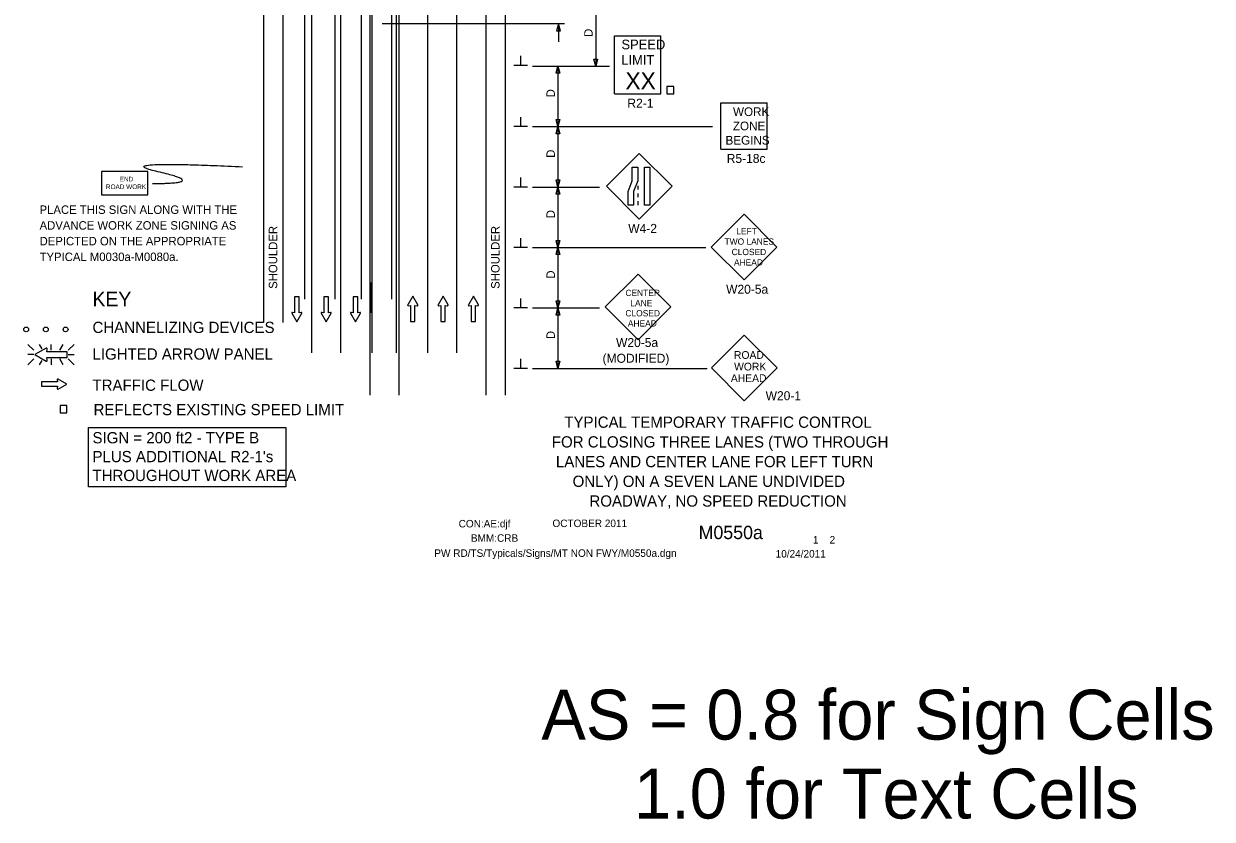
# Model space of a CAD drawing. Extents: x 16731 to 18475, y 7003 to 8262.
# Drawn here: x 16731 to 17714, y 7003 to 7661 of the extents above; entities that cross this region are included whole.
import ezdxf

# ---------------------------------------------------------------- set-up
doc = ezdxf.new("R2010")
doc.units = 0
for name, color, linetype in [('ALI_LEGAL_EX', 7, 'Continuous'), ('BORDER', 7, 'Continuous'), ('BORDER_SIGNAL_WO', 7, 'Continuous'), ('MT_SCRATCH_LEVEL_E', 7, 'Continuous'), ('PAVT_EDGE_EX', 7, 'Continuous'), ('TRAFFIC_SIGNS_PR', 7, 'Continuous'), ('TYPICAL_TEXT_DIMEN_EX', 7, 'Continuous'), ('TYPICAL_TEXT_DIMEN_PR', 7, 'Continuous')]:
    doc.layers.add(name, color=color, linetype=linetype)

msp = doc.modelspace()

# ---------------------------------------------------------------- linework, layer by layer
at = {"layer": 'ALI_LEGAL_EX'}
for p, q in [((16969.24, 7388.68), (16969.24, 8211.76)), ((16993.24, 7388.68), (16993.24, 8211.76)), ((17019.24, 7388.68), (17019.24, 8211.76)), ((17039.24, 7388.68), (17039.24, 8211.76)), ((17065.24, 7388.68), (17065.24, 8211.76)), ((17089.24, 7388.68), (17089.24, 8211.76))]:
    msp.add_line(p, q, dxfattribs=at)
for points in [[(16969.24, 7588.68), (16969.24, 7613.68)], [(16993.24, 7588.68), (16993.24, 7613.68)], [(17019.24, 7588.68), (17019.24, 7613.68)], [(17039.24, 7588.68), (17039.24, 7613.68)], [(17065.24, 7588.68), (17065.24, 7613.68)], [(17089.24, 7588.68), (17089.24, 7613.68)], [(16969.24, 7488.68), (16969.24, 7513.68)], [(16993.24, 7488.68), (16993.24, 7513.68)], [(17019.24, 7488.68), (17019.24, 7513.68)], [(17039.24, 7488.68), (17039.24, 7513.68)], [(17065.24, 7488.68), (17065.24, 7513.68)], [(17089.24, 7488.68), (17089.24, 7513.68)], [(17019.24, 7388.68), (17019.24, 7413.68)], [(17039.24, 7388.68), (17039.24, 7413.68)], [(17065.24, 7388.68), (17065.24, 7413.68)], [(17089.24, 7388.68), (17089.24, 7413.68)]]:
    msp.add_lwpolyline(points, dxfattribs=at)
at = {"layer": 'MT_SCRATCH_LEVEL_E'}
for p, q in [((16958.65, 7435.14), (16954.91, 7435.14)), ((16954.91, 7435.14), (16954.91, 7421.89)), ((16958.65, 7435.14), (16954.91, 7435.14)), ((16954.91, 7435.14), (16954.91, 7421.89)), ((16958.65, 7421.89), (16958.65, 7435.14)), ((16958.65, 7421.89), (16958.65, 7435.14)), ((16982.91, 7435.14), (16979.17, 7435.14)), ((16979.17, 7435.14), (16979.17, 7421.89)), ((16982.91, 7435.14), (16979.17, 7435.14)), ((16979.17, 7435.14), (16979.17, 7421.89)), ((16982.91, 7421.89), (16982.91, 7435.14)), ((16982.91, 7421.89), (16982.91, 7435.14)), ((17007.16, 7435.14), (17003.42, 7435.14)), ((17003.42, 7435.14), (17003.42, 7421.89)), ((17007.16, 7435.14), (17003.42, 7435.14)), ((17003.42, 7435.14), (17003.42, 7421.89)), ((17007.16, 7421.89), (17007.16, 7435.14)), ((17007.16, 7421.89), (17007.16, 7435.14)), ((17052.67, 7435.6), (17048.56, 7428.36)), ((17052.67, 7435.6), (17048.56, 7428.36)), ((17056.82, 7428.36), (17052.67, 7435.6)), ((17056.82, 7428.36), (17052.67, 7435.6)), ((17077.76, 7435.6), (17073.65, 7428.36)), ((17077.76, 7435.6), (17073.65, 7428.36)), ((17081.91, 7428.36), (17077.76, 7435.6)), ((17081.91, 7428.36), (17077.76, 7435.6)), ((17102.85, 7435.6), (17098.74, 7428.36)), ((17102.85, 7435.6), (17098.74, 7428.36)), ((17107, 7428.36), (17102.85, 7435.6)), ((17107, 7428.36), (17102.85, 7435.6)), ((17049.05, 7427.68), (17050.82, 7427.99)), ((17049.05, 7427.68), (17050.82, 7427.99)), ((17050.82, 7427.99), (17050.82, 7414.74)), ((17050.82, 7427.99), (17050.82, 7414.74)), ((17054.56, 7414.74), (17054.56, 7427.99)), ((17054.56, 7427.99), (17056.34, 7427.68)), ((17054.56, 7414.74), (17054.56, 7427.99)), ((17054.56, 7427.99), (17056.34, 7427.68)), ((17074.14, 7427.68), (17075.91, 7427.99)), ((17074.14, 7427.68), (17075.91, 7427.99)), ((17075.91, 7427.99), (17075.91, 7414.74)), ((17075.91, 7427.99), (17075.91, 7414.74)), ((17079.65, 7414.74), (17079.65, 7427.99)), ((17079.65, 7427.99), (17081.43, 7427.68)), ((17079.65, 7414.74), (17079.65, 7427.99)), ((17079.65, 7427.99), (17081.43, 7427.68)), ((17099.22, 7427.68), (17101, 7427.99)), ((17099.22, 7427.68), (17101, 7427.99)), ((17101, 7427.99), (17101, 7414.74)), ((17101, 7427.99), (17101, 7414.74)), ((17104.74, 7414.74), (17104.74, 7427.99)), ((17104.74, 7427.99), (17106.52, 7427.68)), ((17104.74, 7414.74), (17104.74, 7427.99)), ((17104.74, 7427.99), (17106.52, 7427.68)), ((16952.65, 7421.52), (16956.8, 7414.28)), ((16952.65, 7421.52), (16956.8, 7414.28)), ((16954.91, 7421.89), (16953.13, 7422.2)), ((16954.91, 7421.89), (16953.13, 7422.2)), ((16956.8, 7414.28), (16960.91, 7421.52)), ((16956.8, 7414.28), (16960.91, 7421.52)), ((16960.43, 7422.2), (16958.65, 7421.89)), ((16960.43, 7422.2), (16958.65, 7421.89)), ((16976.91, 7421.52), (16981.06, 7414.28)), ((16976.91, 7421.52), (16981.06, 7414.28)), ((16979.17, 7421.89), (16977.39, 7422.2)), ((16979.17, 7421.89), (16977.39, 7422.2)), ((16981.06, 7414.28), (16985.17, 7421.52)), ((16981.06, 7414.28), (16985.17, 7421.52)), ((16984.69, 7422.2), (16982.91, 7421.89)), ((16984.69, 7422.2), (16982.91, 7421.89)), ((17001.17, 7421.52), (17005.31, 7414.28)), ((17001.17, 7421.52), (17005.31, 7414.28)), ((17003.42, 7421.89), (17001.64, 7422.2)), ((17003.42, 7421.89), (17001.64, 7422.2)), ((17005.31, 7414.28), (17009.42, 7421.52)), ((17005.31, 7414.28), (17009.42, 7421.52)), ((17008.94, 7422.2), (17007.16, 7421.89)), ((17008.94, 7422.2), (17007.16, 7421.89)), ((17050.82, 7414.74), (17054.56, 7414.74)), ((17050.82, 7414.74), (17054.56, 7414.74)), ((17075.91, 7414.74), (17079.65, 7414.74)), ((17075.91, 7414.74), (17079.65, 7414.74)), ((17101, 7414.74), (17104.74, 7414.74)), ((17101, 7414.74), (17104.74, 7414.74)), ((16758.95, 7364.79), (16745.69, 7364.79)), ((16745.69, 7364.79), (16745.69, 7361.05)), ((16758.95, 7364.79), (16745.69, 7364.79)), ((16745.69, 7364.79), (16745.69, 7361.05)), ((16758.63, 7366.57), (16758.95, 7364.79)), ((16758.63, 7366.57), (16758.95, 7364.79)), ((16766.56, 7362.94), (16759.32, 7367.05)), ((16766.56, 7362.94), (16759.32, 7367.05)), ((16745.69, 7361.05), (16758.95, 7361.05)), ((16745.69, 7361.05), (16758.95, 7361.05)), ((16758.95, 7361.05), (16758.63, 7359.27)), ((16758.95, 7361.05), (16758.63, 7359.27)), ((16759.32, 7358.79), (16766.56, 7362.94)), ((16759.32, 7358.79), (16766.56, 7362.94))]:
    msp.add_line(p, q, dxfattribs=at)
for centre, start, end in [((17048.97, 7428.14), 150.42484, 279.96381), ((17048.97, 7428.14), 150.42484, 279.96381), ((17056.41, 7428.14), 260.03619, 29.77312), ((17056.41, 7428.14), 260.03619, 29.77312), ((17074.06, 7428.14), 150.42484, 279.96381), ((17074.06, 7428.14), 150.42484, 279.96381), ((17081.5, 7428.14), 260.03619, 29.77312), ((17081.5, 7428.14), 260.03619, 29.77312), ((17099.15, 7428.14), 150.42484, 279.96381), ((17099.15, 7428.14), 150.42484, 279.96381), ((17106.59, 7428.14), 260.03619, 29.77312), ((17106.59, 7428.14), 260.03619, 29.77312), ((16953.06, 7421.74), 80.03619, 209.77312), ((16953.06, 7421.74), 80.03619, 209.77312), ((16960.5, 7421.74), 330.42484, 99.96381), ((16960.5, 7421.74), 330.42484, 99.96381), ((16977.32, 7421.74), 80.03619, 209.77312), ((16977.32, 7421.74), 80.03619, 209.77312), ((16984.76, 7421.74), 330.42484, 99.96381), ((16984.76, 7421.74), 330.42484, 99.96381), ((17001.57, 7421.74), 80.03619, 209.77312), ((17001.57, 7421.74), 80.03619, 209.77312), ((17009.02, 7421.74), 330.42484, 99.96381), ((17009.02, 7421.74), 330.42484, 99.96381), ((16759.09, 7366.64), 60.42484, 189.96381), ((16759.09, 7366.64), 60.42484, 189.96381), ((16759.09, 7359.2), 170.03619, 299.77312), ((16759.09, 7359.2), 170.03619, 299.77312)]:
    msp.add_arc(centre, 0.463, start, end, dxfattribs=at)
at = {"layer": 'PAVT_EDGE_EX'}
for p, q in [((16963.15, 8262.34), (16963.15, 7433.15)), ((16988.15, 8262.34), (16988.15, 7433.15)), ((17010.15, 8262.34), (17010.15, 7433.15)), ((17035.15, 8262.34), (17035.15, 7433.15)), ((16929.24, 8211.76), (16929.24, 7413.89)), ((16945.24, 8211.76), (16945.24, 7413.89)), ((17017.24, 8211.76), (17017.24, 7353.85)), ((17041.24, 8211.76), (17041.24, 7353.85)), ((17113.24, 8211.76), (17113.24, 7353.85)), ((17129.24, 8211.76), (17129.24, 7353.85))]:
    msp.add_line(p, q, dxfattribs=at)
for points in [[(16993.24, 7421.93), (16993.24, 7446.93)], [(17018.24, 7421.93), (17018.24, 7446.93)]]:
    msp.add_lwpolyline(points, dxfattribs=at)
at = {"layer": 'TRAFFIC_SIGNS_PR'}
for p, q in [((17219.61, 7650.98), (17258.01, 7650.98)), ((17219.61, 7602.98), (17219.61, 7650.98)), ((17258.01, 7602.98), (17258.01, 7650.98)), ((17219.61, 7602.98), (17258.01, 7602.98)), ((17307.65, 7557.26), (17307.65, 7595.66)), ((17307.65, 7595.66), (17346.05, 7595.66)), ((17346.05, 7557.26), (17346.05, 7595.66)), ((17240.04, 7553.68), (17212.89, 7526.53)), ((17267.19, 7526.53), (17240.04, 7553.68)), ((17307.65, 7557.26), (17346.05, 7557.26)), ((17212.89, 7526.53), (17240.04, 7499.38)), ((17238.79, 7527.02), (17238.79, 7523.82)), ((17240.04, 7499.38), (17267.19, 7526.53)), ((17238.79, 7520.62), (17238.79, 7517.42)), ((17238.79, 7514.22), (17238.79, 7511.02)), ((17326.8, 7503.39), (17299.65, 7476.23)), ((17353.96, 7476.23), (17326.8, 7503.39)), ((17299.65, 7476.23), (17326.8, 7449.08)), ((17326.8, 7449.08), (17353.96, 7476.23)), ((17239.08, 7453.85), (17211.93, 7426.7)), ((17266.23, 7426.7), (17239.08, 7453.85)), ((17211.93, 7426.7), (17239.08, 7399.55)), ((17239.08, 7399.55), (17266.23, 7426.7)), ((17326.91, 7403.39), (17299.76, 7376.24)), ((17354.07, 7376.24), (17326.91, 7403.39)), ((16734.42, 7395.74), (16739.35, 7390.81)), ((16746.18, 7391.92), (16743.98, 7395.75)), ((16753.5, 7390.81), (16753.5, 7395.75)), ((16760.74, 7390.81), (16763.59, 7395.75)), ((16767.65, 7390.81), (16772.59, 7395.75)), ((16739.35, 7387.26), (16734.42, 7387.26)), ((16734.42, 7378.77), (16739.35, 7383.7)), ((16753.5, 7383.7), (16753.5, 7378.77)), ((16763.63, 7378.77), (16760.78, 7383.7)), ((16767.65, 7387.26), (16772.59, 7387.26)), ((16767.65, 7383.7), (16772.59, 7378.76)), ((16743.93, 7378.77), (16746.04, 7382.43)), ((17299.76, 7376.24), (17326.91, 7349.09)), ((17326.91, 7349.09), (17354.07, 7376.24))]:
    msp.add_line(p, q, dxfattribs=at)
for points in [[(17263.02, 7602.98), (17268.62, 7602.98), (17268.62, 7609.15), (17263.02, 7609.15)], [(17238.79, 7542.27), (17238.79, 7531.09), (17235.45, 7522.2), (17235.45, 7511.02), (17230.95, 7511.02), (17230.95, 7522.2), (17234.3, 7531.09), (17234.3, 7542.27)], [(17248.93, 7542.27), (17248.93, 7511.02), (17244.44, 7511.02), (17244.44, 7542.27)], [(16795.29, 7519.44), (16833.69, 7519.44), (16833.69, 7538.64), (16795.29, 7538.64)], [(16761.02, 7338.99), (16766.61, 7338.99), (16766.61, 7345.16), (16761.02, 7345.16)]]:
    msp.add_lwpolyline(points, close=True, dxfattribs=at)
for points in [[(16749.43, 7392.53), (16740.14, 7387.26), (16749.43, 7381.94)], [(16750.31, 7382.56), (16749.9, 7384.83), (16766.92, 7384.83), (16766.92, 7389.63), (16749.9, 7389.63), (16750.31, 7391.91)]]:
    msp.add_lwpolyline(points, dxfattribs=at)
for centre in [(16732.93, 7408.1), (16749.23, 7408.1), (16765.53, 7408.1)]:
    msp.add_circle(centre, 2, dxfattribs=at)
for centre, radius, start, end in [((16749.72, 7392.01), 0.598, 350.73078, 118.89165), ((16749.72, 7382.46), 0.597, 241.48329, 9.95933)]:
    msp.add_arc(centre, radius, start, end, dxfattribs=at)
msp.add_open_spline([(16837.29, 7528.82), (16884.52, 7528.82), (16799.5, 7548.17), (16911.8, 7542.68)], degree=2, dxfattribs=at)
at = {"layer": 'TYPICAL_TEXT_DIMEN_EX'}
msp.add_lwpolyline([(16784.43, 7326.97), (16947.6, 7326.97), (16947.6, 7278.01), (16784.43, 7278.01)], close=True, dxfattribs=at)
at = {"layer": 'TYPICAL_TEXT_DIMEN_PR'}
for p, q in [((17204.09, 7675.89), (17204.09, 7625.89)), ((17178.24, 7660.97), (17027.46, 7660.97)), ((17173.24, 7660.97), (17171.67, 7655.11)), ((17173.24, 7660.97), (17173.24, 7646.05)), ((17174.81, 7655.11), (17173.24, 7660.97)), ((17171.67, 7655.11), (17173.24, 7655.11)), ((17173.24, 7655.11), (17174.81, 7655.11)), ((17142, 7626.54), (17142, 7634.33)), ((17204.09, 7625.89), (17202.52, 7631.76)), ((17202.52, 7631.76), (17204.09, 7631.76)), ((17204.09, 7631.76), (17205.66, 7631.76)), ((17205.66, 7631.76), (17204.09, 7625.89)), ((17147.62, 7626.54), (17136.37, 7626.54)), ((17151.87, 7625.89), (17215.42, 7625.89)), ((17171.3, 7620.03), (17172.87, 7625.89)), ((17172.87, 7620.03), (17171.3, 7620.03)), ((17172.87, 7625.89), (17172.87, 7575.89)), ((17172.87, 7625.89), (17174.44, 7620.03)), ((17174.44, 7620.03), (17172.87, 7620.03)), ((17142, 7575.89), (17142, 7583.68)), ((17172.87, 7575.89), (17171.3, 7581.76)), ((17171.3, 7581.76), (17172.87, 7581.76)), ((17172.87, 7581.76), (17174.44, 7581.76)), ((17174.44, 7581.76), (17172.87, 7575.89)), ((17147.62, 7575.89), (17136.37, 7575.89)), ((17151.87, 7575.89), (17300.7, 7575.89)), ((17171.3, 7570.03), (17172.87, 7575.89)), ((17172.87, 7575.89), (17172.87, 7525.89)), ((17172.87, 7575.89), (17174.44, 7570.03)), ((17172.87, 7570.03), (17171.3, 7570.03)), ((17174.44, 7570.03), (17172.87, 7570.03)), ((17142, 7525.89), (17142, 7533.68)), ((17172.87, 7525.89), (17171.3, 7531.76)), ((17171.3, 7531.76), (17172.87, 7531.76)), ((17172.87, 7531.76), (17174.44, 7531.76)), ((17174.44, 7531.76), (17172.87, 7525.89)), ((17147.62, 7525.89), (17136.37, 7525.89)), ((17151.87, 7525.89), (17207.23, 7525.89)), ((17171.3, 7520.03), (17172.87, 7525.89)), ((17172.87, 7525.89), (17172.87, 7475.89)), ((17172.87, 7525.89), (17174.44, 7520.03)), ((17172.87, 7520.03), (17171.3, 7520.03)), ((17174.44, 7520.03), (17172.87, 7520.03)), ((17142, 7475.89), (17142, 7483.68)), ((17147.62, 7475.89), (17136.37, 7475.89)), ((17151.87, 7475.89), (17295.31, 7475.89)), ((17172.87, 7475.89), (17171.3, 7481.76)), ((17171.3, 7481.76), (17172.87, 7481.76)), ((17171.3, 7470.03), (17172.87, 7475.89)), ((17172.87, 7481.76), (17174.44, 7481.76)), ((17174.44, 7481.76), (17172.87, 7475.89)), ((17172.87, 7475.89), (17172.87, 7425.89)), ((17172.87, 7475.89), (17174.44, 7470.03)), ((17172.87, 7470.03), (17171.3, 7470.03)), ((17174.44, 7470.03), (17172.87, 7470.03)), ((17142, 7425.89), (17142, 7433.68)), ((17147.62, 7425.89), (17136.37, 7425.89)), ((17151.87, 7425.89), (17207.23, 7425.89)), ((17172.87, 7425.89), (17171.3, 7431.76)), ((17171.3, 7431.76), (17172.87, 7431.76)), ((17171.3, 7420.03), (17172.87, 7425.89)), ((17172.87, 7431.76), (17174.44, 7431.76)), ((17174.44, 7431.76), (17172.87, 7425.89)), ((17172.87, 7425.89), (17172.87, 7375.89)), ((17172.87, 7425.89), (17174.44, 7420.03)), ((17172.87, 7420.03), (17171.3, 7420.03)), ((17174.44, 7420.03), (17172.87, 7420.03)), ((17142, 7375.89), (17142, 7383.68)), ((17147.62, 7375.89), (17136.37, 7375.89)), ((17151.87, 7375.89), (17296.29, 7375.89)), ((17172.87, 7375.89), (17171.3, 7381.76)), ((17171.3, 7381.76), (17172.87, 7381.76)), ((17172.87, 7381.76), (17174.44, 7381.76)), ((17174.44, 7381.76), (17172.87, 7375.89))]:
    msp.add_line(p, q, dxfattribs=at)

# ---------------------------------------------------------------- texts
at = {"layer": 'BORDER'}
for s, p in [('TYPICAL TEMPORARY TRAFFIC CONTROL', (17178.09, 7326.72)), ('FOR CLOSING THREE LANES (TWO THROUGH', (17167.78, 7310.42)), ('LANES AND CENTER LANE FOR LEFT TURN', (17171.14, 7294.12)), ('ONLY) ON A SEVEN LANE UNDIVIDED', (17184.98, 7277.82)), ('ROADWAY, NO SPEED REDUCTION', (17198.9, 7261.52))]:
    msp.add_text(s, height=9.3, dxfattribs=at).set_placement(p)
at = {"layer": 'BORDER_SIGNAL_WO'}
for s, height, p in [('CON:AE:djf', 6.2, (17090.69, 7244.31)), ('    OCTOBER 2011    ', 6.2, (17159.08, 7244.59)), ('BMM:CRB   ', 6.2, (17100.81, 7232.42)), ('    M0550a   ', 11, (17272.86, 7234.63)), (' 1    2 ', 6.2, (17381.45, 7230.95)), ('PW RD/TS/Typicals/Signs/MT NON FWY/M0550a.dgn    ', 6.2, (17070.55, 7219.96)), ('10/24/2011    ', 6.2, (17352.93, 7219.38)), ('AS = 0.8 for Sign Cells', 41.2877, (17159.1, 7068.77)), ('     1.0 for Text Cells', 41.2877, (17159.1, 7003.48))]:
    msp.add_text(s, height=height, dxfattribs=at).set_placement(p)
at = {"layer": 'TRAFFIC_SIGNS_PR'}
for s, height, p in [('SPEED', 8, (17225.37, 7639.84)), ('LIMIT', 8, (17225.21, 7627.04)), ('XX', 14.031, (17228.72, 7606.73)), ('R2-1', 7.44, (17230.28, 7591.54)), ('WORK', 7.217, (17317.65, 7584.62)), ('ZONE', 7.217, (17317.53, 7572.81)), ('BEGINS', 7.217, (17311.46, 7561)), ('R5-18c', 7.44, (17312.46, 7545.82)), ('END', 3.831, (16810.3, 7530.57)), ('ROAD WORK', 3.831, (16798.9, 7524.19)), ('PLACE THIS SIGN ALONG WITH THE', 7, (16744.01, 7503.66)), ('ADVANCE WORK ZONE SIGNING AS', 7, (16744.01, 7490.66)), ('W4-2', 7.44, (17231, 7487.94)), ('LEFT', 5.2, (17320.34, 7486.77)), ('DEPICTED ON THE APPROPRIATE', 7, (16744.01, 7477.66)), ('TWO LANES', 5.2, (17310.66, 7478.17)), ('CLOSED', 5.2, (17316.52, 7469.57)), ('TYPICAL M0030a-M0080a.', 7, (16744.01, 7464.66)), ('AHEAD', 5.2, (17318.46, 7460.97)), ('W20-5a', 7.44, (17311.94, 7437.64)), ('CENTER', 5.2, (17228.66, 7435.7)), ('CLOSED', 5.2, (17228.66, 7418.9)), ('LANE', 5.2, (17232.73, 7427.31)), ('AHEAD', 5.2, (17230.68, 7410.51)), ('W20-5a', 7.44, (17220.89, 7393.55)), ('(MODIFIED)', 7.44, (17209.75, 7380.51)), ('ROAD', 6.4, (17318.46, 7383.77)), ('WORK', 6.4, (17318.56, 7374.17)), ('AHEAD', 6.4, (17315.87, 7364.57)), ('W20-1', 7.44, (17344.65, 7349.54))]:
    msp.add_text(s, height=height, dxfattribs=at).set_placement(p)
at = {"layer": 'TYPICAL_TEXT_DIMEN_EX'}
for s, height, p in [('KEY', 12, (16787.77, 7427.21)), ('CHANNELIZING DEVICES', 9.3, (16787.77, 7405.16)), ('LIGHTED ARROW PANEL', 9.3, (16787.77, 7383.11)), ('TRAFFIC FLOW', 9.3, (16787.77, 7357.31)), ('REFLECTS EXISTING SPEED LIMIT', 9.3, (16788.65, 7337.15)), ('SIGN = 200 ft2 - TYPE B', 9.3, (16787.77, 7313.86)), ("PLUS ADDITIONAL R2-1's", 9.3, (16787.77, 7298.26)), ('THROUGHOUT WORK AREA', 9.3, (16787.77, 7282.66))]:
    msp.add_text(s, height=height, dxfattribs=at).set_placement(p)
at = {"layer": 'TYPICAL_TEXT_DIMEN_PR'}
for s, p in [('D', (17201.53, 7650.11)), ('D', (17170.31, 7600.11)), ('D', (17170.31, 7550.11)), ('D', (17170.31, 7500.11)), ('D', (17170.31, 7500.11)), ('SHOULDER', (16940.62, 7441.71)), ('SHOULDER', (17124.52, 7441.71)), ('D', (17170.31, 7450.11)), ('D', (17170.31, 7400.11))]:
    msp.add_text(s, height=7, rotation=90, dxfattribs=at).set_placement(p)

doc.saveas('drawing.dxf')
